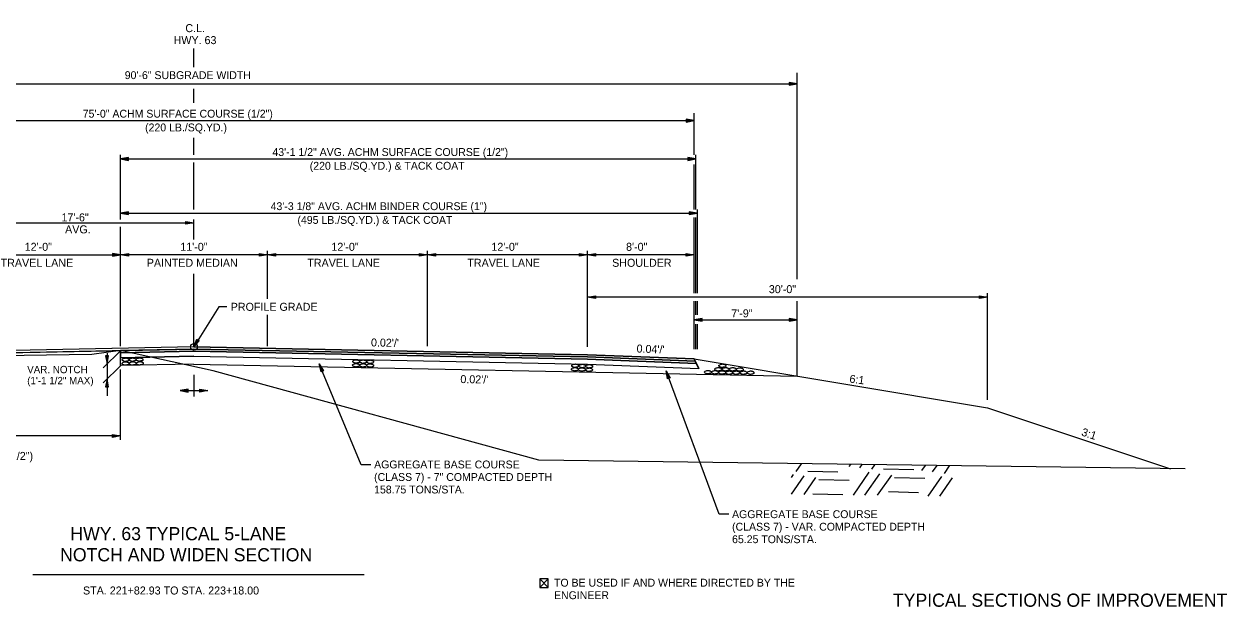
# Model space of a CAD drawing. Extents: x 1461846 to 1462006, y 1686171 to 1686805.
# Drawn here: x 1461912.3 to 1462002.5, y 1686437 to 1686480.8 of the extents above; entities that cross this region are included whole.
import ezdxf

# ---------------------------------------------------------------- set-up
doc = ezdxf.new("R2010")
doc.units = 0
for name, color, linetype in [('1', 7, 'Continuous'), ('10', 7, 'Continuous'), ('12', 7, 'Continuous'), ('19', 7, 'Continuous'), ('20', 7, 'Continuous'), ('3', 7, 'Continuous'), ('42', 7, 'Continuous'), ('R_Draft', 7, 'Continuous')]:
    doc.layers.add(name, color=color, linetype=linetype)

# ---------------------------------------------------------------- blocks, each defined once
blk = doc.blocks.new('ROCKS')
at = {"layer": '1'}
blk.add_spline([(0.013, 0.06), (0.053, 0.053), (0.107, 0.033), (0.133, 0.013), (0.133, -0.007), (0.12, -0.033), (0.107, -0.04), (0.073, -0.053), (0.033, -0.067), (0.013, -0.067), (-0.02, -0.06), (-0.06, -0.053), (-0.087, -0.047), (-0.113, -0.02), (-0.113, -0.007), (-0.107, 0.02), (-0.087, 0.033), (-0.067, 0.047), (-0.033, 0.053), (-0.02, 0.06), (0.013, 0.06)], degree=3, dxfattribs=at)

msp = doc.modelspace()

# ---------------------------------------------------------------- linework, layer by layer
at = {"layer": '10'}
for p, q in [((1461951.582, 1686439.129), (1461950.941, 1686438.488)), ((1461950.941, 1686439.129), (1461951.582, 1686438.488))]:
    msp.add_line(p, q, dxfattribs=at)
msp.add_lwpolyline([(1461951.334, 1686438.488), (1461951.582, 1686438.488), (1461951.582, 1686439.129), (1461950.941, 1686439.129), (1461950.941, 1686438.488), (1461951.323, 1686438.488)], dxfattribs=at)
at = {"layer": '19'}
for p, q in [((1461925.014, 1686477.56), (1461925.014, 1686478.951)), ((1461925.014, 1686474.882), (1461925.014, 1686475.928)), ((1461925.014, 1686470.978), (1461925.014, 1686472.256)), ((1461925.014, 1686466.858), (1461925.014, 1686470.392)), ((1461925.014, 1686464.609), (1461925.014, 1686466.125)), ((1461925.014, 1686456.555), (1461925.014, 1686462.044)), ((1461918.599, 1686455.88), (1461918.389, 1686455.88)), ((1461918.389, 1686455.88), (1461918.494, 1686455.28)), ((1461918.444, 1686455.88), (1461918.479, 1686455.44)), ((1461918.494, 1686455.28), (1461918.599, 1686455.88)), ((1461918.509, 1686455.44), (1461918.549, 1686455.88)), ((1461919.514, 1686456.112), (1461919.514, 1686455.737)), ((1461962.514, 1686455.645), (1461962.876, 1686454.922)), ((1461937.545, 1686447.697), (1461934.411, 1686455.272)), ((1461934.543, 1686454.679), (1461934.411, 1686455.272)), ((1461934.411, 1686455.272), (1461934.737, 1686454.758)), ((1461934.589, 1686454.699), (1461934.457, 1686455.119)), ((1461934.483, 1686455.13), (1461934.687, 1686454.74)), ((1461934.737, 1686454.758), (1461934.543, 1686454.679)), ((1461964.39, 1686443.994), (1461960.425, 1686454.749)), ((1461960.534, 1686454.151), (1461960.425, 1686454.749)), ((1461960.425, 1686454.749), (1461960.73, 1686454.222)), ((1461960.58, 1686454.169), (1461960.464, 1686454.594)), ((1461960.491, 1686454.604), (1461960.679, 1686454.207)), ((1461962.876, 1686454.922), (1461962.684, 1686455.305)), ((1461962.684, 1686455.305), (1461962.684, 1686455.305)), ((1461962.876, 1686454.922), (1461962.876, 1686454.922)), ((1461918.494, 1686454.155), (1461918.389, 1686453.555)), ((1461918.479, 1686453.995), (1461918.439, 1686453.555)), ((1461918.599, 1686453.555), (1461918.494, 1686454.155)), ((1461918.544, 1686453.555), (1461918.509, 1686453.995)), ((1461960.73, 1686454.222), (1461960.534, 1686454.151)), ((1461918.389, 1686453.555), (1461918.599, 1686453.555)), ((1461938.282, 1686447.697), (1461937.545, 1686447.697)), ((1461970.161, 1686447.206), (1461970.561, 1686447.783)), ((1461974.152, 1686447.583), (1461974.26, 1686447.732)), ((1461974.945, 1686447.48), (1461975.115, 1686447.722)), ((1461975.839, 1686447.375), (1461976.07, 1686447.711)), ((1461976.727, 1686447.392), (1461978.987, 1686447.348)), ((1461979.602, 1686447.266), (1461979.869, 1686447.658)), ((1461980.395, 1686447.163), (1461980.734, 1686447.647)), ((1461981.289, 1686447.058), (1461981.678, 1686447.627)), ((1461969.814, 1686446.743), (1461969.971, 1686446.966)), ((1461969.819, 1686445.494), (1461970.765, 1686446.863)), ((1461970.774, 1686445.483), (1461971.659, 1686446.758)), ((1461971.05, 1686447.233), (1461973.309, 1686447.179)), ((1461971.881, 1686446.591), (1461974.14, 1686446.538)), ((1461974.473, 1686445.431), (1461975.65, 1686447.136)), ((1461975.328, 1686445.422), (1461976.443, 1686447.033)), ((1461976.283, 1686445.41), (1461977.337, 1686446.928)), ((1461977.548, 1686446.752), (1461979.818, 1686446.707)), ((1461980.083, 1686445.357), (1461981.1, 1686446.818)), ((1461980.937, 1686445.347), (1461981.893, 1686446.715)), ((1461977.091, 1686445.688), (1461979.35, 1686445.634)), ((1461971.412, 1686445.519), (1461973.683, 1686445.474)), ((1461965.127, 1686443.994), (1461964.39, 1686443.994))]:
    msp.add_line(p, q, dxfattribs=at)
for points in [[(1461887.429, 1686455.475), (1461895.514, 1686455.798), (1461925.014, 1686456.388), (1461954.514, 1686455.798), (1461962.599, 1686455.475), (1461962.514, 1686455.645), (1461954.514, 1686455.965), (1461925.014, 1686456.555), (1461895.514, 1686455.965), (1461887.514, 1686455.645)], [(1461919.513, 1686456.112), (1461919.513, 1686456.112), (1461925.013, 1686456.222), (1461954.513, 1686455.632), (1461962.684, 1686455.305), (1461962.599, 1686455.475), (1461954.513, 1686455.798), (1461925.013, 1686456.388), (1461919.514, 1686456.278), (1461919.514, 1686456.112)]]:
    msp.add_lwpolyline(points, close=True, dxfattribs=at)
for points in [[(1461962.684, 1686455.305), (1461954.513, 1686455.632), (1461925.013, 1686456.222), (1461919.514, 1686456.112), (1461919.514, 1686456.112)], [(1461919.514, 1686455.737), (1461919.514, 1686455.737), (1461925.013, 1686455.847), (1461954.513, 1686455.257), (1461962.876, 1686454.922)]]:
    msp.add_lwpolyline(points, dxfattribs=at)
at = {"layer": '20'}
for p, q in [((1461970.238, 1686472.581), (1461970.238, 1686477.131)), ((1461879.798, 1686476.307), (1461970.238, 1686476.307)), ((1461969.638, 1686476.412), (1461969.638, 1686476.202)), ((1461970.238, 1686476.307), (1461969.638, 1686476.412)), ((1461970.078, 1686476.322), (1461969.638, 1686476.357)), ((1461969.638, 1686476.202), (1461970.238, 1686476.307)), ((1461969.638, 1686476.252), (1461970.078, 1686476.292)), ((1461887.514, 1686473.537), (1461962.514, 1686473.537)), ((1461961.914, 1686473.643), (1461961.914, 1686473.433)), ((1461962.514, 1686473.537), (1461961.914, 1686473.643)), ((1461962.354, 1686473.552), (1461961.914, 1686473.588)), ((1461961.914, 1686473.433), (1461962.514, 1686473.537)), ((1461961.914, 1686473.483), (1461962.354, 1686473.522)), ((1461962.514, 1686470.978), (1461962.514, 1686474.105)), ((1461970.238, 1686461.628), (1461970.238, 1686472.581)), ((1461919.514, 1686466.125), (1461919.514, 1686470.978)), ((1461962.639, 1686466.858), (1461962.639, 1686470.978)), ((1461920.114, 1686470.764), (1461919.514, 1686470.659)), ((1461919.514, 1686470.659), (1461954.639, 1686470.659)), ((1461919.514, 1686470.659), (1461920.114, 1686470.554)), ((1461920.114, 1686470.709), (1461919.674, 1686470.674)), ((1461919.674, 1686470.644), (1461920.114, 1686470.604)), ((1461920.114, 1686470.554), (1461920.114, 1686470.764)), ((1461954.639, 1686470.659), (1461962.639, 1686470.659)), ((1461962.039, 1686470.764), (1461962.039, 1686470.554)), ((1461962.639, 1686470.659), (1461962.039, 1686470.764)), ((1461962.479, 1686470.674), (1461962.039, 1686470.709)), ((1461962.039, 1686470.554), (1461962.639, 1686470.659)), ((1461962.039, 1686470.604), (1461962.479, 1686470.644)), ((1461962.514, 1686466.858), (1461962.514, 1686470.248)), ((1461920.114, 1686466.697), (1461919.514, 1686466.592)), ((1461919.514, 1686466.592), (1461920.114, 1686466.487)), ((1461919.514, 1686466.592), (1461954.775, 1686466.592)), ((1461920.114, 1686466.642), (1461919.674, 1686466.607)), ((1461919.674, 1686466.577), (1461920.114, 1686466.537)), ((1461920.114, 1686466.487), (1461920.114, 1686466.697)), ((1461954.775, 1686466.59), (1461962.775, 1686466.59)), ((1461962.157, 1686466.698), (1461962.157, 1686466.488)), ((1461962.757, 1686466.593), (1461962.157, 1686466.698)), ((1461962.597, 1686466.608), (1461962.157, 1686466.643)), ((1461962.157, 1686466.488), (1461962.757, 1686466.593)), ((1461962.157, 1686466.538), (1461962.597, 1686466.578)), ((1461962.775, 1686460.586), (1461962.775, 1686466.858)), ((1461919.514, 1686463.765), (1461919.514, 1686465.568)), ((1461925.014, 1686465.767), (1461925.014, 1686466.125)), ((1461962.514, 1686463.766), (1461962.514, 1686466.263)), ((1461962.639, 1686460.586), (1461962.639, 1686466.263)), ((1461919.514, 1686456.744), (1461919.514, 1686462.044)), ((1461962.639, 1686458.957), (1461962.639, 1686459.986)), ((1461962.775, 1686458.957), (1461962.775, 1686459.986)), ((1461970.238, 1686454.358), (1461970.238, 1686459.986)), ((1461963.122, 1686458.693), (1461962.522, 1686458.588)), ((1461962.522, 1686458.588), (1461970.238, 1686458.588)), ((1461962.522, 1686458.588), (1461963.122, 1686458.483)), ((1461962.639, 1686456.383), (1461962.639, 1686458.257)), ((1461963.122, 1686458.638), (1461962.682, 1686458.603)), ((1461962.682, 1686458.573), (1461963.122, 1686458.533)), ((1461962.775, 1686456.383), (1461962.775, 1686458.257)), ((1461963.122, 1686458.483), (1461963.122, 1686458.693)), ((1461969.638, 1686458.693), (1461969.638, 1686458.483)), ((1461970.238, 1686458.588), (1461969.638, 1686458.693)), ((1461970.078, 1686458.603), (1461969.638, 1686458.638)), ((1461969.638, 1686458.483), (1461970.238, 1686458.588)), ((1461969.638, 1686458.533), (1461970.078, 1686458.573)), ((1461919.518, 1686456.282), (1461918.195, 1686454.987)), ((1461919.518, 1686455.157), (1461918.195, 1686453.862))]:
    msp.add_line(p, q, dxfattribs=at)
msp.add_lwpolyline([(1461918.494, 1686456.071), (1461918.494, 1686452.874)], dxfattribs=at)
at = {"layer": '3'}
msp.add_line((1461912.93, 1686439.466), (1461937.786, 1686439.466), dxfattribs=at)
at = {"layer": 'R_Draft'}
for p, q in [((1461907.514, 1686465.864), (1461925.014, 1686465.864)), ((1461924.414, 1686465.759), (1461924.414, 1686465.969)), ((1461924.414, 1686465.969), (1461925.014, 1686465.864)), ((1461924.414, 1686465.914), (1461924.854, 1686465.879)), ((1461925.014, 1686465.864), (1461924.414, 1686465.759)), ((1461924.854, 1686465.849), (1461924.414, 1686465.809)), ((1461918.914, 1686463.57), (1461918.914, 1686463.36)), ((1461919.514, 1686463.465), (1461918.914, 1686463.57)), ((1461919.514, 1686456.615), (1461919.514, 1686463.765)), ((1461919.514, 1686463.465), (1461920.114, 1686463.57)), ((1461920.114, 1686463.57), (1461920.114, 1686463.36)), ((1461929.914, 1686463.36), (1461929.914, 1686463.57)), ((1461929.914, 1686463.57), (1461930.514, 1686463.465)), ((1461930.514, 1686460.16), (1461930.514, 1686463.765)), ((1461930.514, 1686463.465), (1461931.114, 1686463.57)), ((1461931.114, 1686463.57), (1461931.114, 1686463.36)), ((1461941.914, 1686463.36), (1461941.914, 1686463.57)), ((1461941.914, 1686463.57), (1461942.514, 1686463.465)), ((1461942.514, 1686456.615), (1461942.514, 1686463.765)), ((1461942.514, 1686463.465), (1461943.114, 1686463.57)), ((1461943.114, 1686463.57), (1461943.114, 1686463.36)), ((1461953.914, 1686463.36), (1461953.914, 1686463.57)), ((1461953.914, 1686463.57), (1461954.514, 1686463.465)), ((1461953.914, 1686463.36), (1461953.914, 1686463.57)), ((1461953.914, 1686463.57), (1461954.514, 1686463.465)), ((1461953.914, 1686463.36), (1461953.914, 1686463.57)), ((1461953.914, 1686463.57), (1461954.514, 1686463.465)), ((1461954.514, 1686456.561), (1461954.514, 1686463.765)), ((1461954.514, 1686463.465), (1461955.114, 1686463.57)), ((1461955.114, 1686463.57), (1461955.114, 1686463.36)), ((1461961.914, 1686463.36), (1461961.914, 1686463.57)), ((1461961.914, 1686463.57), (1461962.514, 1686463.465)), ((1461962.514, 1686460.586), (1461962.514, 1686463.765)), ((1461907.514, 1686463.465), (1461919.514, 1686463.465)), ((1461919.354, 1686463.48), (1461918.914, 1686463.515)), ((1461918.914, 1686463.36), (1461919.514, 1686463.465)), ((1461918.914, 1686463.41), (1461919.354, 1686463.45)), ((1461930.514, 1686463.465), (1461919.514, 1686463.465)), ((1461920.114, 1686463.36), (1461919.514, 1686463.465)), ((1461919.674, 1686463.48), (1461920.114, 1686463.515)), ((1461920.114, 1686463.41), (1461919.674, 1686463.45)), ((1461929.914, 1686463.515), (1461930.354, 1686463.48)), ((1461930.514, 1686463.465), (1461929.914, 1686463.36)), ((1461930.354, 1686463.45), (1461929.914, 1686463.41)), ((1461942.514, 1686463.465), (1461930.514, 1686463.465)), ((1461931.114, 1686463.36), (1461930.514, 1686463.465)), ((1461930.674, 1686463.48), (1461931.114, 1686463.515)), ((1461931.114, 1686463.41), (1461930.674, 1686463.45)), ((1461941.914, 1686463.515), (1461942.354, 1686463.48)), ((1461942.514, 1686463.465), (1461941.914, 1686463.36)), ((1461942.354, 1686463.45), (1461941.914, 1686463.41)), ((1461954.514, 1686463.465), (1461942.514, 1686463.465)), ((1461943.114, 1686463.36), (1461942.514, 1686463.465)), ((1461942.674, 1686463.48), (1461943.114, 1686463.515)), ((1461943.114, 1686463.41), (1461942.674, 1686463.45)), ((1461953.914, 1686463.515), (1461954.354, 1686463.48)), ((1461953.914, 1686463.515), (1461954.354, 1686463.48)), ((1461953.914, 1686463.515), (1461954.354, 1686463.48)), ((1461954.514, 1686463.465), (1461953.914, 1686463.36)), ((1461954.514, 1686463.465), (1461953.914, 1686463.36)), ((1461954.514, 1686463.465), (1461953.914, 1686463.36)), ((1461954.354, 1686463.45), (1461953.914, 1686463.41)), ((1461954.354, 1686463.45), (1461953.914, 1686463.41)), ((1461954.354, 1686463.45), (1461953.914, 1686463.41)), ((1461962.514, 1686463.465), (1461954.514, 1686463.465)), ((1461955.114, 1686463.36), (1461954.514, 1686463.465)), ((1461954.674, 1686463.48), (1461955.114, 1686463.515)), ((1461955.114, 1686463.41), (1461954.674, 1686463.45)), ((1461961.914, 1686463.515), (1461962.354, 1686463.48)), ((1461962.514, 1686463.465), (1461961.914, 1686463.36)), ((1461962.354, 1686463.45), (1461961.914, 1686463.41)), ((1461954.514, 1686460.286), (1461955.114, 1686460.391)), ((1461984.514, 1686460.286), (1461954.514, 1686460.286)), ((1461955.114, 1686460.181), (1461954.514, 1686460.286)), ((1461954.674, 1686460.301), (1461955.114, 1686460.336)), ((1461955.114, 1686460.231), (1461954.674, 1686460.271)), ((1461955.114, 1686460.391), (1461955.114, 1686460.181)), ((1461962.514, 1686456.383), (1461962.514, 1686459.986)), ((1461983.914, 1686460.181), (1461983.914, 1686460.391)), ((1461983.914, 1686460.391), (1461984.514, 1686460.286)), ((1461983.914, 1686460.336), (1461984.354, 1686460.301)), ((1461984.514, 1686460.286), (1461983.914, 1686460.181)), ((1461984.354, 1686460.271), (1461983.914, 1686460.231)), ((1461984.514, 1686452.583), (1461984.514, 1686460.586)), ((1461930.514, 1686456.615), (1461930.514, 1686458.96)), ((1461925.014, 1686456.555), (1461895.514, 1686455.965)), ((1461925.014, 1686456.388), (1461898.514, 1686455.858)), ((1461925.009, 1686456.557), (1461925.233, 1686457.124)), ((1461925.411, 1686457.014), (1461925.009, 1686456.557)), ((1461925.014, 1686456.555), (1461954.514, 1686455.965)), ((1461925.014, 1686456.388), (1461954.514, 1686455.798)), ((1461925.083, 1686456.698), (1461925.276, 1686457.092)), ((1461925.37, 1686457.036), (1461925.106, 1686456.687)), ((1461925.233, 1686457.124), (1461925.411, 1686457.014)), ((1461919.514, 1686455.153), (1461919.514, 1686456.278)), ((1461925.014, 1686456.222), (1461919.514, 1686456.112)), ((1461925.014, 1686455.847), (1461919.514, 1686455.737)), ((1461925.014, 1686456.222), (1461954.514, 1686455.632)), ((1461925.014, 1686455.847), (1461954.514, 1686455.257)), ((1461954.514, 1686455.965), (1461962.514, 1686455.645)), ((1461954.514, 1686455.798), (1461962.599, 1686455.475)), ((1461954.514, 1686455.632), (1461954.684, 1686455.625)), ((1461954.514, 1686455.632), (1461962.684, 1686455.305)), ((1461962.514, 1686455.645), (1461984.514, 1686451.978)), ((1461924.986, 1686455.263), (1461919.514, 1686455.153)), ((1461919.514, 1686449.567), (1461919.514, 1686454.853)), ((1461924.986, 1686455.263), (1461970.238, 1686454.358)), ((1461954.514, 1686455.257), (1461954.876, 1686455.242)), ((1461954.514, 1686455.257), (1461962.876, 1686454.922)), ((1461925.014, 1686454.45), (1461925.014, 1686452.818)), ((1461924.567, 1686453.374), (1461923.967, 1686453.269)), ((1461923.967, 1686453.269), (1461924.567, 1686453.164)), ((1461923.967, 1686453.269), (1461926.062, 1686453.269)), ((1461924.567, 1686453.319), (1461924.127, 1686453.284)), ((1461924.127, 1686453.254), (1461924.567, 1686453.214)), ((1461924.567, 1686453.164), (1461924.567, 1686453.374)), ((1461925.462, 1686453.164), (1461925.462, 1686453.374)), ((1461925.462, 1686453.374), (1461926.062, 1686453.269)), ((1461925.462, 1686453.319), (1461925.902, 1686453.284)), ((1461926.062, 1686453.269), (1461925.462, 1686453.164)), ((1461925.902, 1686453.254), (1461925.462, 1686453.214)), ((1461984.514, 1686451.978), (1461998.247, 1686447.401)), ((1461919.514, 1686449.867), (1461895.514, 1686449.867)), ((1461918.914, 1686449.761), (1461918.914, 1686449.971)), ((1461918.914, 1686449.971), (1461919.514, 1686449.867)), ((1461918.914, 1686449.916), (1461919.354, 1686449.882)), ((1461919.514, 1686449.867), (1461918.914, 1686449.761)), ((1461919.354, 1686449.852), (1461918.914, 1686449.811))]:
    msp.add_line(p, q, dxfattribs=at)
for points in [[(1461927.469, 1686459.56), (1461926.869, 1686459.56), (1461925.014, 1686456.555)], [(1461950.863, 1686448.051), (1461926.446, 1686454.761), (1461919.514, 1686456.278), (1461917.357, 1686455.991), (1461898.673, 1686455.704), (1461895.514, 1686455.798), (1461892.913, 1686455.285), (1461876.611, 1686451.414), (1461867.661, 1686453.131), (1461849.809, 1686453.192)], [(1461999.344, 1686447.386), (1461950.863, 1686448.051)]]:
    msp.add_lwpolyline(points, dxfattribs=at)
msp.add_circle((1461925.014, 1686456.555), 0.25, dxfattribs=at)

# ---------------------------------------------------------------- block references
at = {"layer": '19', "xscale": 2.061136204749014}
for p, yscale, rotation in [((1461919.901, 1686455.594), -2.061136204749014, -179.20800457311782), ((1461919.905, 1686455.311), -2.061136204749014, -179.20800457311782), ((1461920.432, 1686455.601), -2.061136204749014, -179.20800457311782), ((1461920.436, 1686455.319), -2.061136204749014, -179.20800457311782), ((1461920.954, 1686455.608), -2.061136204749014, -179.20800457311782), ((1461920.97, 1686455.326), -2.061136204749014, -179.20800457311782), ((1461937.192, 1686455.462), -2.0611362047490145, 178.9116607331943), ((1461937.722, 1686455.452), -2.0611362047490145, 178.9116607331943), ((1461938.244, 1686455.442), -2.0611362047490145, 178.9116607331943), ((1461937.186, 1686455.18), -2.0611362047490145, 178.9116607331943), ((1461937.717, 1686455.17), -2.0611362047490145, 178.9116607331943), ((1461938.25, 1686455.159), -2.0611362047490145, 178.9116607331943), ((1461953.601, 1686454.881), -2.061136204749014, 180), ((1461953.618, 1686455.142), -2.061136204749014, 180), ((1461954.131, 1686454.861), -2.061136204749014, 180), ((1461954.148, 1686455.123), -2.061136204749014, 180), ((1461954.659, 1686454.842), -2.061136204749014, 180), ((1461954.676, 1686455.104), -2.061136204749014, 180), ((1461963.576, 1686454.661), -2.061136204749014, 180), ((1461964.109, 1686454.651), -2.061136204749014, 180), ((1461964.356, 1686454.878), -2.061136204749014, 180), ((1461964.633, 1686454.638), -2.061136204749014, 180), ((1461964.657, 1686455.142), -2.061136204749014, 180), ((1461964.898, 1686454.878), -2.061136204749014, 180), ((1461965.164, 1686454.623), -2.061136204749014, 180), ((1461965.432, 1686454.878), -2.061136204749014, 180), ((1461965.691, 1686454.623), -2.061136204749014, 180), ((1461965.975, 1686454.862), -2.061136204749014, 180), ((1461966.235, 1686454.623), -2.061136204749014, 180), ((1461966.773, 1686454.623), -2.061136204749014, 180)]:
    msp.add_blockref('ROCKS', p, dxfattribs=dict(at, yscale=yscale, rotation=rotation))

# ---------------------------------------------------------------- texts
at = {"layer": '10'}
for s, p in [('VAR. NOTCH', (1461912.505, 1686454.577)), ('(1\'-1 1/2" MAX)', (1461912.505, 1686453.748))]:
    msp.add_text(s, height=0.55, dxfattribs=at).set_placement(p)
for s, height, rotation, p in [('STA. 221+82.93 TO STA. 223+18.00', 0.6, 359.99538, (1461916.69, 1686437.966)), ('TO BE USED IF AND WHERE DIRECTED BY THE ', 0.59001, 360, (1461952.014, 1686438.556)), ('ENGINEER', 0.59, 360, (1461952.014, 1686437.616))]:
    msp.add_text(s, height=height, rotation=rotation, dxfattribs=at).set_placement(p)
at = {"layer": '12'}
for s, p in [('HWY. 63 TYPICAL 5-LANE', (1461915.742, 1686442.037)), ('NOTCH AND WIDEN SECTION', (1461914.974, 1686440.454))]:
    msp.add_text(s, height=0.98999, rotation=359.99538, dxfattribs=at).set_placement(p)
at = {"layer": '19'}
for s, height, p in [('AGGREGATE BASE COURSE', 0.59001, (1461938.521, 1686447.431)), ('(CLASS 7) - 7" COMPACTED DEPTH', 0.59001, (1461938.521, 1686446.491)), ('158.75 TONS/STA.', 0.59001, (1461938.521, 1686445.551)), ('AGGREGATE BASE COURSE', 0.59001, (1461965.366, 1686443.699)), ('(CLASS 7) - VAR. COMPACTED DEPTH', 0.59001, (1461965.366, 1686442.759)), ('65.25 TONS/STA.', 0.59001, (1461965.366, 1686441.819)), ('TYPICAL SECTIONS OF IMPROVEMENT', 0.98999, (1461977.425, 1686437.043))]:
    msp.add_text(s, height=height, rotation=360, dxfattribs=at).set_placement(p)
at = {"layer": '42'}
for s, p in [('90\'-6" SUBGRADE WIDTH', (1461919.819, 1686476.656)), ('75\'-0" ACHM SURFACE COURSE (1/2")', (1461916.669, 1686473.763)), ('(220 LB./SQ.YD.)', (1461921.347, 1686472.73)), ('43\'-1 1/2" AVG. ACHM SURFACE COURSE (1/2")', (1461930.895, 1686470.884)), ('(220 LB./SQ.YD.) & TACK COAT', (1461933.694, 1686469.852)), ('43\'-3 1/8" AVG. ACHM BINDER COURSE (1")', (1461930.759, 1686466.82)), ('(495 LB./SQ.YD.) & TACK COAT', (1461932.773, 1686465.788))]:
    msp.add_text(s, height=0.59001, rotation=360, dxfattribs=at).set_placement(p)
at = {"layer": 'R_Draft'}
for s, rotation, p in [('C.L.', 360, (1461924.366, 1686480.18)), ('HWY. 63', 360, (1461923.487, 1686479.28)), ('17\'-6"', 360, (1461915.076, 1686465.975)), ('AVG.', 360, (1461915.348, 1686465.075)), ('12\'-0"', 360, (1461912.317, 1686463.765)), ('TRAVEL LANE', 360, (1461910.514, 1686462.565)), ('PROFILE GRADE', 360, (1461927.769, 1686459.26)), ('7\'-9"', 360, (1461965.305, 1686458.771)), ("0.02'/'", 358.85424, (1461938.282, 1686456.59)), ("0.04'/'", 357.70939, (1461958.195, 1686456.135)), ("0.02'/'", 358.85424, (1461944.986, 1686453.839)), ('6:1', 352.48657, (1461974.142, 1686453.88)), ('3:1', 341.56505, (1461991.518, 1686449.916))]:
    msp.add_text(s, height=0.6, rotation=rotation, dxfattribs=at).set_placement(p)
for s, p in [('11\'-0"', (1461923.987, 1686463.765)), ('12\'-0"', (1461935.317, 1686463.765)), ('12\'-0"', (1461947.317, 1686463.765)), ('8\'-0"', (1461957.416, 1686463.765)), ('PAINTED MEDIAN', (1461921.473, 1686462.565)), ('TRAVEL LANE', (1461933.514, 1686462.565)), ('TRAVEL LANE', (1461945.514, 1686462.565)), ('SHOULDER', (1461956.372, 1686462.565)), ('30\'-0"', (1461968.123, 1686460.586)), ('ACHM SURFACE COURSE (1/2")', (1461900.716, 1686448.067))]:
    msp.add_text(s, height=0.6, dxfattribs=at).set_placement(p)

doc.saveas('drawing.dxf')
